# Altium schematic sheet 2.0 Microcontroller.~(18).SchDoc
size A4; SheetNumber: 2; SheetTotal: 7
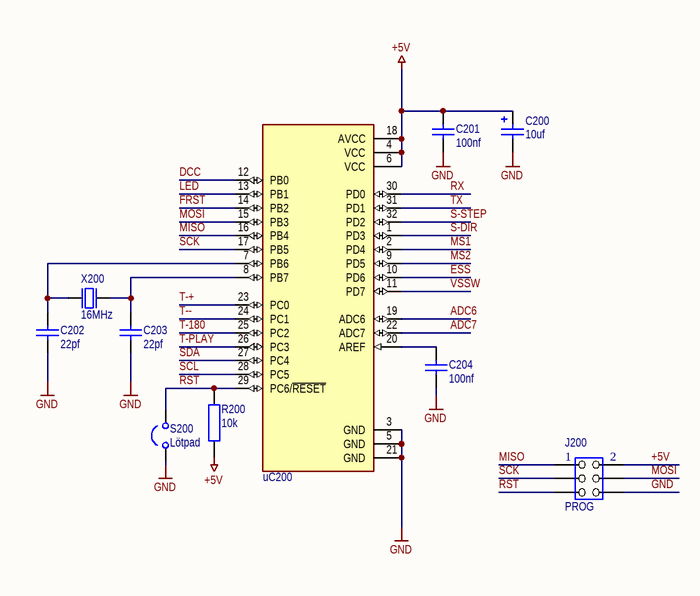
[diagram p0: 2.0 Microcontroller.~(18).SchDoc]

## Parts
C200  10uf  [C_SMD_C-TYP]
C201  100nf  [C_SMD_0805]
C202  22pf  [C_SMD_0805]
C203  22pf  [C_SMD_0805]
C204  100nf  [C_SMD_0805]
J200  PROG  [J_2x3]
R200  10k  [R_SMD_0805]
S200  Lötpad  [S_SMD_Pad-NO]
uC200  ATMega328(p)-AU  [TQFP-32]  (value not drawn)
X200  16MHz  [X_SMD_XTAL]

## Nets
+5V: C200.1 C201.1 J200.2 R200.1 uC200.4(VCC) uC200.6(VCC) uC200.18(AVCC)
GND: C200.2 C201.2 C202.2 C203.2 C204.2 J200.6 S200.1 uC200.3(GND) uC200.5(GND) uC200.21(GND)
ADC6: uC200.19(ADC6)
ADC7: uC200.22(ADC7)
DCC: uC200.12(PB0)
ESS: uC200.10(PD6)
FRST: uC200.14(PB2)
LED: uC200.13(PB1)
MISO: J200.1 uC200.16(PB4)
MOSI: J200.4 uC200.15(PB3)
MS1: uC200.2(PD4)
MS2: uC200.9(PD5)
RST: J200.5 R200.2 S200.2 uC200.29(PC6/~{RESET})
RX: uC200.30(PD0)
S-DIR: uC200.1(PD3)
S-STEP: uC200.32(PD2)
SCK: J200.3 uC200.17(PB5)
SCL: uC200.28(PC5)
SDA: uC200.27(PC4)
T-180: uC200.25(PC2)
T-+: uC200.23(PC0)
T--: uC200.24(PC1)
T-PLAY: uC200.26(PC3)
TX: uC200.31(PD1)
VSSW: uC200.11(PD7)
NetC202_1: C202.1 uC200.7(PB6) X200.1
NetC203_1: C203.1 uC200.8(PB7) X200.2
NetC204_1: C204.1 uC200.20(AREF)

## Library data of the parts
C200 = C_SMD_ELK: SMD Elektrolytkondensator
C201-C204 = C_SMD_KO: Kondensator SMD Universal, Keramik, Folie, usw.
J200 = J_THT_IDC 2x3: Stecker
R200 = R_SMD_Widerstand: Widerstand SMD
S200 = S_SMD_Jumper: Lötverbinder
uC200 = UC_ATMega328P-AU: Microcontroller
X200 = X_SMD_Quarz: Quarz SMD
